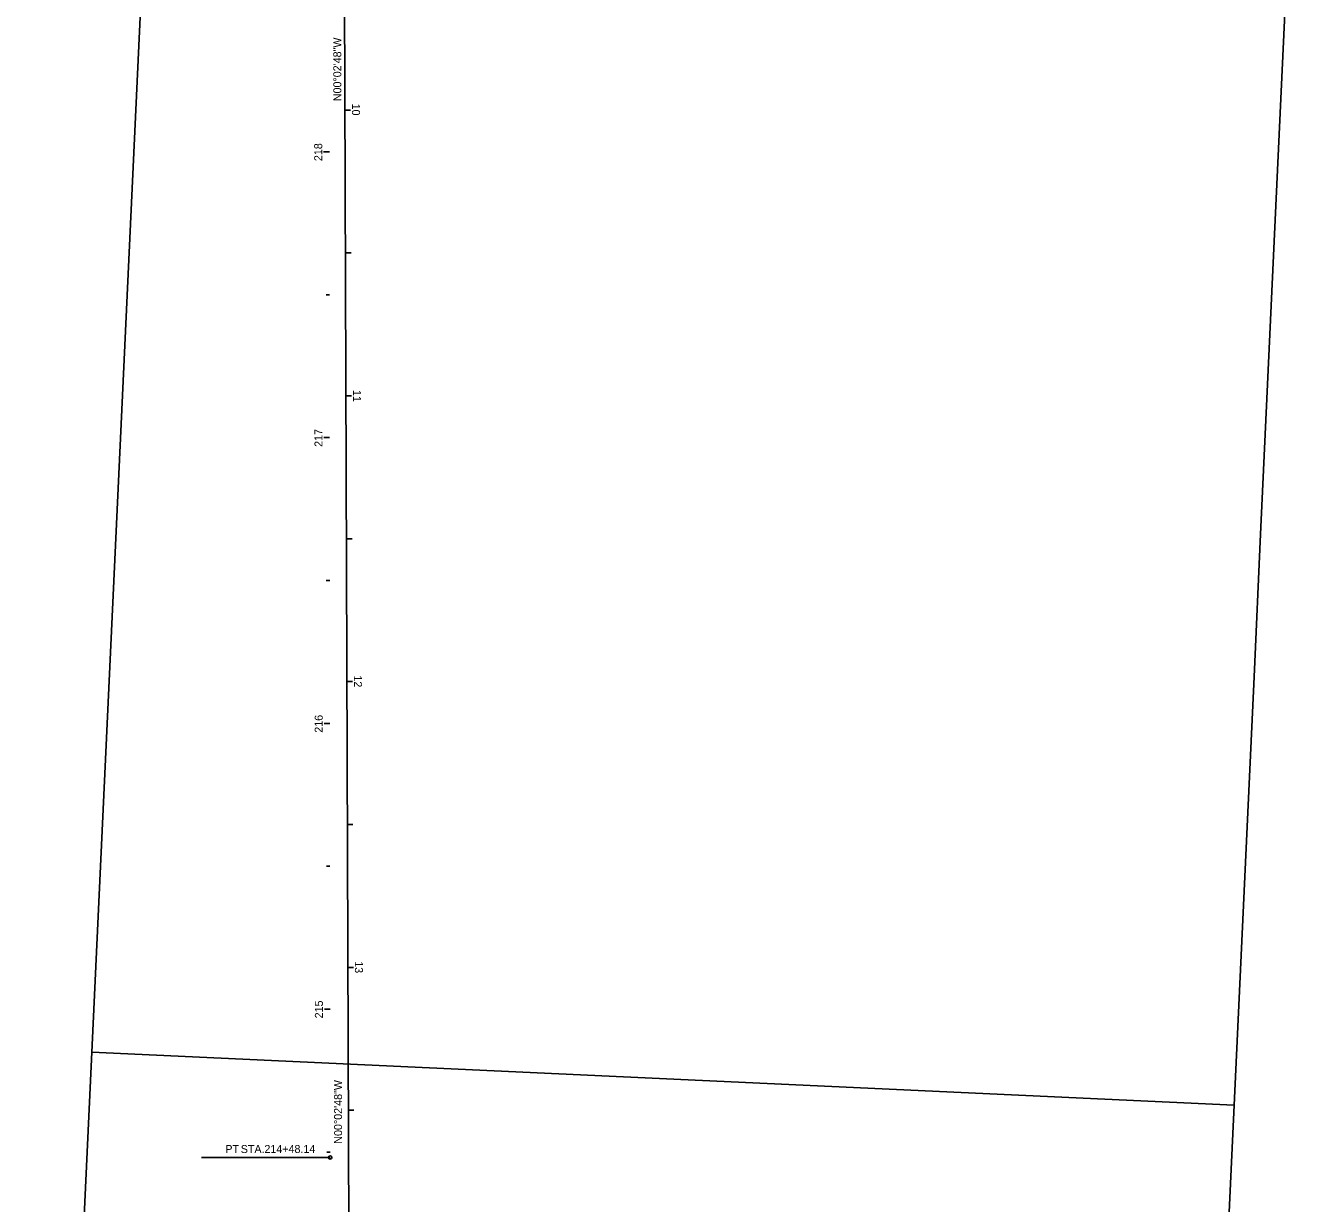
# Model space of a CAD drawing. Extents: x 172043 to 172958, y 249504 to 260295.
# Drawn here: x 172405.2 to 172851.2, y 258353.8 to 258766 of the extents above; entities that cross this region are included whole.
import ezdxf

# ---------------------------------------------------------------- set-up
doc = ezdxf.new("R2010")
doc.units = 0
for name, color, linetype in [('DR_X_Storm_Sewer', 7, 'Continuous'), ('PV_X_EOP', 7, 'Continuous'), ('RW_X_CL_100_Distances', 7, 'Continuous'), ('SC_Scratch1', 7, 'Continuous'), ('SV_X_Shot_Marker', 7, 'Continuous')]:
    doc.layers.add(name, color=color, linetype=linetype)

msp = doc.modelspace()

# ---------------------------------------------------------------- linework, layer by layer
at = {"layer": 'DR_X_Storm_Sewer'}
for points in [[(172428.41, 258406.85), (172827.98, 258388.27), (172830.3, 258438.22), (172832.63, 258488.16), (172834.95, 258538.11), (172837.27, 258588.06), (172839.59, 258638), (172841.92, 258687.95), (172844.24, 258737.89), (172846.56, 258787.84), (172848.88, 258837.79), (172851.21, 258887.73), (172451.64, 258906.31), (172449.32, 258856.37), (172446.99, 258806.42), (172444.67, 258756.48), (172442.35, 258706.53), (172440.03, 258656.58), (172437.7, 258606.64), (172435.38, 258556.69), (172433.06, 258506.75), (172430.74, 258456.8)], [(172405.19, 257907.39), (172804.75, 257888.81), (172807.08, 257938.76), (172809.4, 257988.7), (172811.72, 258038.65), (172814.04, 258088.6), (172816.37, 258138.54), (172818.69, 258188.49), (172821.01, 258238.43), (172823.34, 258288.38), (172825.66, 258338.33), (172827.98, 258388.27), (172428.41, 258406.85), (172426.09, 258356.91), (172423.77, 258306.96), (172421.44, 258257.02), (172419.12, 258207.07), (172416.8, 258157.12), (172414.48, 258107.18), (172412.15, 258057.23), (172409.83, 258007.29), (172407.51, 257957.34)]]:
    msp.add_lwpolyline(points, close=True, dxfattribs=at)
at = {"layer": 'PV_X_EOP'}
for p, q in [((172511.49, 258721.83), (172509.49, 258721.83)), ((172511.53, 258671.83), (172510.33, 258671.83)), ((172511.57, 258621.83), (172509.57, 258621.83)), ((172511.61, 258571.83), (172510.41, 258571.83)), ((172511.65, 258521.83), (172509.65, 258521.83)), ((172511.69, 258471.83), (172510.49, 258471.83)), ((172511.73, 258421.83), (172509.73, 258421.83)), ((172511.77, 258371.83), (172510.57, 258371.83))]:
    msp.add_line(p, q, dxfattribs=at)
at = {"layer": 'SC_Scratch1'}
for p, q in [((172513.49, 259736.44), (172518.63, 258228.95)), ((172516.9, 258736.44), (172518.9, 258736.45)), ((172517.07, 258686.44), (172519.07, 258686.45)), ((172517.24, 258636.44), (172519.24, 258636.45)), ((172517.41, 258586.44), (172519.41, 258586.45)), ((172517.58, 258536.45), (172519.58, 258536.45)), ((172517.75, 258486.45), (172519.75, 258486.45)), ((172517.92, 258436.45), (172519.92, 258436.45)), ((172518.1, 258386.45), (172520.1, 258386.45))]:
    msp.add_line(p, q, dxfattribs=at)
at = {"layer": 'SV_X_Shot_Marker'}
msp.add_line((172511.77, 258369.97), (172466.77, 258369.93), dxfattribs=at)
msp.add_circle((172511.77, 258369.97), 0.6, dxfattribs=at)

# ---------------------------------------------------------------- texts
at = {"layer": 'PV_X_EOP'}
for s, p in [('218', (172508.99, 258718.58)), ('217', (172509.07, 258618.59)), ('216', (172509.15, 258518.57)), ('215', (172509.23, 258418.62))]:
    msp.add_text(s, height=2.8, rotation=90.0466, dxfattribs=at).set_placement(p)
at = {"layer": 'RW_X_CL_100_Distances'}
for p in [(172515.67, 258739.54), (172515.93, 258374.77)]:
    msp.add_text('N00°02\'48"W', height=2.8, rotation=90.0466, dxfattribs=at).set_placement(p)
at = {"layer": 'SC_Scratch1'}
for s, p in [('10', (172519.39, 258738.68)), ('11', (172519.74, 258638.49)), ('12', (172520.08, 258538.62)), ('13', (172520.42, 258438.61))]:
    msp.add_text(s, height=2.8, rotation=270.1955, dxfattribs=at).set_placement(p)
at = {"layer": 'SV_X_Shot_Marker'}
for s, p in [('PT', (172475.1, 258371.51)), (' STA. ', (172479.45, 258371.51)), ('214+48.14', (172488.77, 258371.52))]:
    msp.add_text(s, height=2.8, rotation=0.0466, dxfattribs=at).set_placement(p)

doc.saveas('drawing.dxf')
